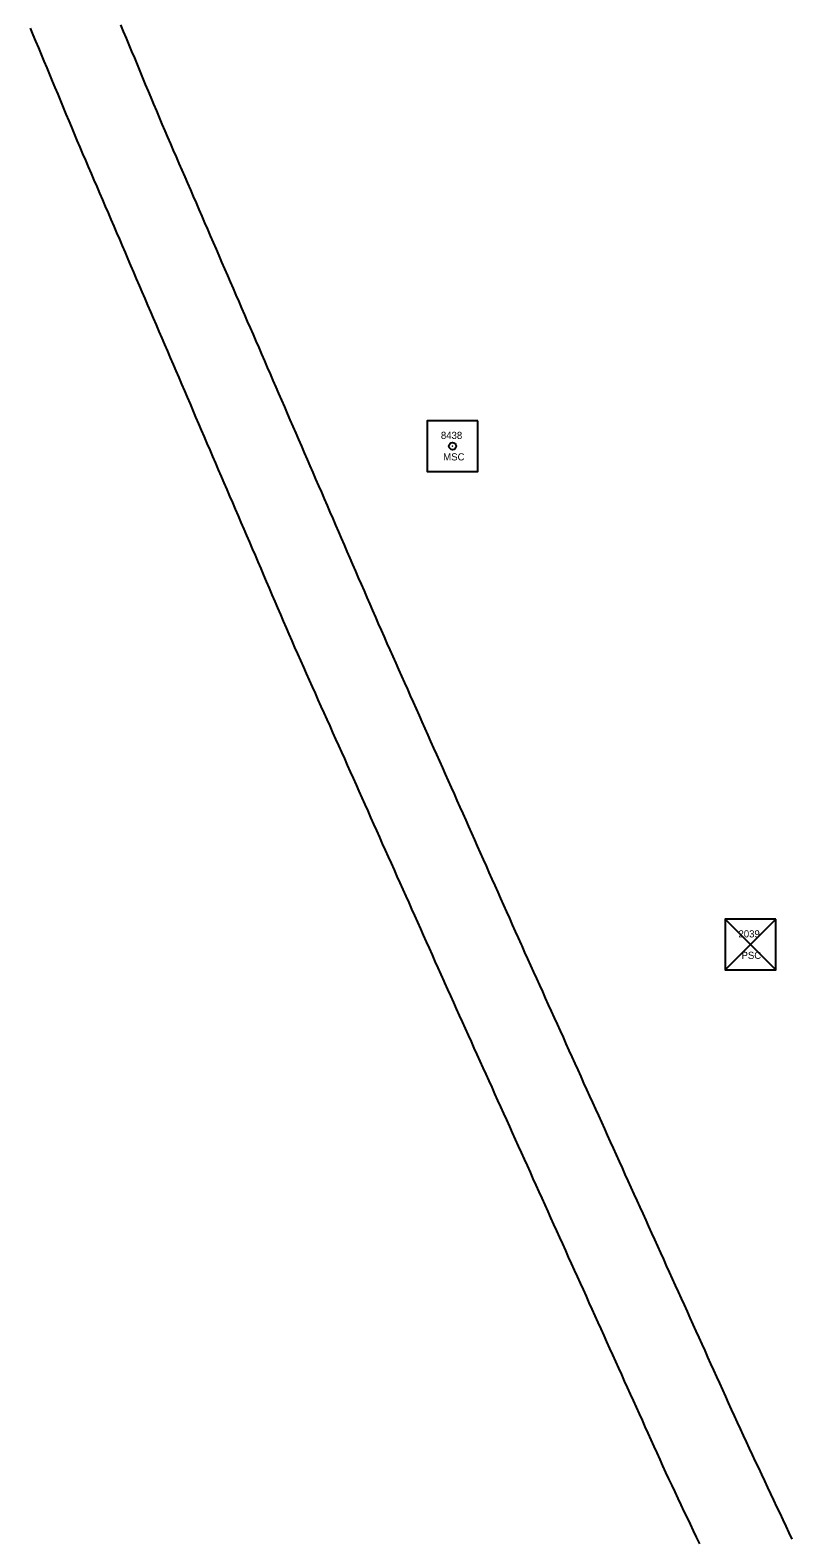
# Model space of a CAD drawing. Extents: x 205929 to 2357175, y -1785700 to 846739.
# Drawn here: x 2011940.5 to 2012046.8, y 825874.3 to 826084.7 of the extents above; entities that cross this region are included whole.
import ezdxf

# ---------------------------------------------------------------- set-up
doc = ezdxf.new("R2010")
doc.units = 0
for name, color, linetype in [('RD_HC_Survey', 7, 'Continuous'), ('RD_HC_txCode', 7, 'Continuous'), ('RD_Sketch1', 7, 'Continuous'), ('RD_SMD_Locator', 7, 'Continuous')]:
    doc.layers.add(name, color=color, linetype=linetype)

msp = doc.modelspace()

# ---------------------------------------------------------------- linework, layer by layer
at = {"layer": 'RD_HC_Survey'}
for p, q in [((2012037.49, 825960.58), (2012044.56, 825953.51)), ((2012044.56, 825960.58), (2012037.49, 825953.51)), ((2012044.56, 825960.58), (2012037.49, 825960.58)), ((2012037.49, 825960.58), (2012041.03, 825957.05)), ((2012041.03, 825957.05), (2012044.56, 825960.58)), ((2012041.03, 825957.05), (2012037.49, 825953.51)), ((2012044.56, 825953.51), (2012041.03, 825957.05)), ((2012037.49, 825953.51), (2012044.56, 825953.51))]:
    msp.add_line(p, q, dxfattribs=at)
for points in [[(2012002.98, 826030.15), (2011995.91, 826030.15), (2011995.91, 826023.08), (2012002.98, 826023.08)], [(2012044.56, 825960.58), (2012037.49, 825960.58), (2012037.49, 825953.51), (2012044.56, 825953.51)]]:
    msp.add_lwpolyline(points, close=True, dxfattribs=at)
msp.add_circle((2011999.44, 826026.62), 0.5, dxfattribs=at)
at = {"layer": 'RD_Sketch1'}
for points in [[(2011953.09, 826085.4), (2011953.47, 826084.48), (2011953.86, 826083.56), (2011954.24, 826082.63), (2011954.62, 826081.71), (2011955.01, 826080.79), (2011955.39, 826079.86), (2011955.77, 826078.94), (2011956.16, 826078.02), (2011956.54, 826077.09), (2011956.93, 826076.17), (2011957.31, 826075.25), (2011957.69, 826074.32), (2011958.08, 826073.4), (2011958.46, 826072.48), (2011958.86, 826071.56), (2011959.25, 826070.64), (2011959.65, 826069.72), (2011960.05, 826068.8), (2011960.45, 826067.89), (2011960.84, 826066.97), (2011961.24, 826066.05), (2011961.64, 826065.13), (2011962.04, 826064.22), (2011962.43, 826063.3), (2011962.83, 826062.38), (2011963.23, 826061.46), (2011963.63, 826060.55), (2011964.02, 826059.63), (2011964.42, 826058.71), (2011964.82, 826057.79), (2011965.22, 826056.88), (2011965.61, 826055.96), (2011966.01, 826055.04), (2011966.41, 826054.12), (2011966.81, 826053.21), (2011967.2, 826052.29), (2011967.6, 826051.37), (2011968, 826050.45), (2011968.4, 826049.54), (2011968.79, 826048.62), (2011969.19, 826047.7), (2011969.59, 826046.78), (2011969.99, 826045.87), (2011970.38, 826044.95), (2011970.78, 826044.03), (2011971.18, 826043.11), (2011971.58, 826042.2), (2011971.97, 826041.28), (2011972.37, 826040.36), (2011972.77, 826039.44), (2011973.17, 826038.53), (2011973.56, 826037.61), (2011973.96, 826036.69), (2011974.36, 826035.77), (2011974.76, 826034.86), (2011975.15, 826033.94), (2011975.55, 826033.02), (2011975.95, 826032.1), (2011976.35, 826031.19), (2011976.74, 826030.27), (2011977.14, 826029.35), (2011977.54, 826028.43), (2011977.94, 826027.52), (2011978.33, 826026.6), (2011978.73, 826025.68), (2011979.13, 826024.76), (2011979.53, 826023.85), (2011979.92, 826022.93), (2011980.32, 826022.01), (2011980.72, 826021.09), (2011981.12, 826020.18), (2011981.51, 826019.26), (2011981.91, 826018.34), (2011982.31, 826017.42), (2011982.71, 826016.51), (2011983.1, 826015.59), (2011983.5, 826014.67), (2011983.9, 826013.75), (2011984.3, 826012.84), (2011984.69, 826011.92), (2011985.09, 826011), (2011985.49, 826010.08), (2011985.89, 826009.17), (2011986.28, 826008.25), (2011986.68, 826007.33), (2011987.08, 826006.41), (2011987.48, 826005.5), (2011987.87, 826004.58), (2011988.27, 826003.66), (2011988.67, 826002.74), (2011989.07, 826001.83), (2011989.47, 826000.91), (2011989.87, 826000), (2011990.28, 825999.08), (2011990.69, 825998.17), (2011991.09, 825997.26), (2011991.5, 825996.34), (2011991.91, 825995.43), (2011992.31, 825994.52), (2011992.72, 825993.6), (2011993.13, 825992.69), (2011993.53, 825991.78), (2011993.94, 825990.86), (2011994.35, 825989.95), (2011994.76, 825989.04), (2011995.16, 825988.12), (2011995.57, 825987.21), (2011995.98, 825986.3), (2011996.38, 825985.38), (2011996.79, 825984.47), (2011997.2, 825983.56), (2011997.6, 825982.64), (2011998.01, 825981.73), (2011998.42, 825980.82), (2011998.83, 825979.9), (2011999.23, 825978.99), (2011999.64, 825978.08), (2012000.05, 825977.16), (2012000.45, 825976.25), (2012000.86, 825975.34), (2012001.27, 825974.42), (2012001.67, 825973.51), (2012002.08, 825972.6), (2012002.49, 825971.68), (2012002.89, 825970.77), (2012003.3, 825969.86), (2012003.71, 825968.94), (2012004.12, 825968.03), (2012004.52, 825967.12), (2012004.93, 825966.2), (2012005.34, 825965.29), (2012005.74, 825964.38), (2012006.15, 825963.46), (2012006.56, 825962.55), (2012006.96, 825961.63), (2012007.37, 825960.72), (2012007.78, 825959.81), (2012008.19, 825958.89), (2012008.59, 825957.98), (2012009, 825957.07), (2012009.09, 825956.86), (2012009.5, 825955.95), (2012009.91, 825955.04), (2012010.33, 825954.13), (2012010.74, 825953.22), (2012011.15, 825952.31), (2012011.56, 825951.4), (2012011.98, 825950.49), (2012012.39, 825949.58), (2012012.8, 825948.66), (2012013.21, 825947.75), (2012013.62, 825946.84), (2012014.04, 825945.93), (2012014.45, 825945.02), (2012014.86, 825944.11), (2012015.27, 825943.2), (2012015.68, 825942.29), (2012016.1, 825941.38), (2012016.51, 825940.46), (2012016.92, 825939.55), (2012017.33, 825938.64), (2012017.74, 825937.73), (2012018.16, 825936.82), (2012018.57, 825935.91), (2012018.98, 825935), (2012019.39, 825934.09), (2012019.81, 825933.18), (2012020.22, 825932.27), (2012020.63, 825931.35), (2012021.04, 825930.44), (2012021.45, 825929.53), (2012021.87, 825928.62), (2012022.28, 825927.71), (2012022.69, 825926.8), (2012023.1, 825925.89), (2012023.51, 825924.98), (2012023.93, 825924.07), (2012024.34, 825923.16), (2012024.75, 825922.24), (2012025.16, 825921.33), (2012025.57, 825920.42), (2012025.99, 825919.51), (2012026.4, 825918.6), (2012026.81, 825917.69), (2012027.22, 825916.78), (2012027.64, 825915.87), (2012028.05, 825914.96), (2012028.46, 825914.05), (2012028.87, 825913.13), (2012029.28, 825912.22), (2012029.7, 825911.31), (2012030.11, 825910.4), (2012030.52, 825909.49), (2012030.93, 825908.58), (2012031.34, 825907.67), (2012031.76, 825906.76), (2012032.17, 825905.85), (2012032.58, 825904.94), (2012032.99, 825904.02), (2012033.41, 825903.11), (2012033.82, 825902.2), (2012034.23, 825901.29), (2012034.64, 825900.38), (2012035.05, 825899.47), (2012035.47, 825898.56), (2012035.88, 825897.65), (2012036.29, 825896.74), (2012036.7, 825895.83), (2012037.11, 825894.91), (2012037.53, 825894), (2012037.94, 825893.09), (2012038.35, 825892.18), (2012038.76, 825891.27), (2012039.17, 825890.36), (2012039.59, 825889.45), (2012040, 825888.54), (2012040.43, 825887.63), (2012040.85, 825886.73), (2012041.28, 825885.82), (2012041.7, 825884.92), (2012042.13, 825884.02), (2012042.56, 825883.11), (2012042.98, 825882.21), (2012043.41, 825881.3), (2012043.83, 825880.4), (2012044.26, 825879.49), (2012044.68, 825878.59), (2012045.11, 825877.68), (2012045.54, 825876.78), (2012045.96, 825875.87), (2012046.39, 825874.97), (2012046.81, 825874.06)], [(2011940.46, 826084.96), (2011940.85, 826084.03), (2011941.23, 826083.11), (2011941.62, 826082.19), (2011942, 826081.26), (2011942.39, 826080.34), (2011942.77, 826079.42), (2011943.16, 826078.5), (2011943.54, 826077.57), (2011943.92, 826076.65), (2011944.31, 826075.73), (2011944.69, 826074.8), (2011945.08, 826073.88), (2011945.46, 826072.96), (2011945.85, 826072.03), (2011946.23, 826071.11), (2011946.62, 826070.19), (2011947, 826069.27), (2011947.39, 826068.35), (2011947.79, 826067.43), (2011948.18, 826066.51), (2011948.58, 826065.59), (2011948.97, 826064.67), (2011949.37, 826063.75), (2011949.76, 826062.83), (2011950.15, 826061.91), (2011950.55, 826060.99), (2011950.94, 826060.08), (2011951.34, 826059.16), (2011951.73, 826058.24), (2011952.13, 826057.32), (2011952.52, 826056.4), (2011952.92, 826055.48), (2011953.31, 826054.56), (2011953.71, 826053.64), (2011954.1, 826052.73), (2011954.49, 826051.81), (2011954.89, 826050.89), (2011955.28, 826049.97), (2011955.68, 826049.05), (2011956.07, 826048.13), (2011956.47, 826047.21), (2011956.86, 826046.29), (2011957.26, 826045.37), (2011957.65, 826044.46), (2011958.05, 826043.54), (2011958.44, 826042.62), (2011958.84, 826041.7), (2011959.23, 826040.78), (2011959.62, 826039.86), (2011960.02, 826038.94), (2011960.41, 826038.02), (2011960.81, 826037.11), (2011961.2, 826036.19), (2011961.6, 826035.27), (2011961.99, 826034.35), (2011962.39, 826033.43), (2011962.78, 826032.51), (2011963.18, 826031.59), (2011963.57, 826030.67), (2011963.96, 826029.75), (2011964.36, 826028.84), (2011964.75, 826027.92), (2011965.15, 826027), (2011965.54, 826026.08), (2011965.94, 826025.16), (2011966.33, 826024.24), (2011966.73, 826023.32), (2011967.12, 826022.4), (2011967.52, 826021.49), (2011967.91, 826020.57), (2011968.3, 826019.65), (2011968.7, 826018.73), (2011969.09, 826017.81), (2011969.49, 826016.89), (2011969.88, 826015.97), (2011970.28, 826015.05), (2011970.67, 826014.14), (2011971.07, 826013.22), (2011971.46, 826012.3), (2011971.86, 826011.38), (2011972.25, 826010.46), (2011972.65, 826009.54), (2011973.04, 826008.62), (2011973.43, 826007.7), (2011973.83, 826006.78), (2011974.22, 826005.87), (2011974.62, 826004.95), (2011975.01, 826004.03), (2011975.41, 826003.11), (2011975.8, 826002.19), (2011976.2, 826001.27), (2011976.59, 826000.35), (2011976.99, 825999.43), (2011977.39, 825998.52), (2011977.8, 825997.61), (2011978.2, 825996.69), (2011978.61, 825995.78), (2011979.02, 825994.87), (2011979.43, 825993.95), (2011979.84, 825993.04), (2011980.24, 825992.13), (2011980.65, 825991.22), (2011981.06, 825990.3), (2011981.47, 825989.39), (2011981.88, 825988.48), (2011982.29, 825987.56), (2011982.69, 825986.65), (2011983.1, 825985.74), (2011983.51, 825984.83), (2011983.92, 825983.91), (2011984.33, 825983), (2011984.73, 825982.09), (2011985.14, 825981.17), (2011985.55, 825980.26), (2011985.96, 825979.35), (2011986.37, 825978.44), (2011986.78, 825977.52), (2011987.18, 825976.61), (2011987.59, 825975.7), (2011988, 825974.78), (2011988.41, 825973.87), (2011988.82, 825972.96), (2011989.23, 825972.05), (2011989.63, 825971.13), (2011990.04, 825970.22), (2011990.45, 825969.31), (2011990.86, 825968.39), (2011991.27, 825967.48), (2011991.67, 825966.57), (2011992.08, 825965.66), (2011992.49, 825964.74), (2011992.9, 825963.83), (2011993.31, 825962.92), (2011993.72, 825962), (2011994.12, 825961.09), (2011994.53, 825960.18), (2011994.94, 825959.27), (2011995.35, 825958.35), (2011995.76, 825957.44), (2011996.16, 825956.53), (2011996.57, 825955.61), (2011996.98, 825954.7), (2011997.39, 825953.79), (2011997.8, 825952.88), (2011998.21, 825951.96), (2011998.32, 825951.72), (2011998.73, 825950.8), (2011999.14, 825949.89), (2011999.55, 825948.98), (2011999.96, 825948.07), (2012000.37, 825947.16), (2012000.79, 825946.25), (2012001.2, 825945.34), (2012001.61, 825944.43), (2012002.02, 825943.51), (2012002.43, 825942.6), (2012002.84, 825941.69), (2012003.25, 825940.78), (2012003.67, 825939.87), (2012004.08, 825938.96), (2012004.49, 825938.05), (2012004.9, 825937.14), (2012005.31, 825936.22), (2012005.72, 825935.31), (2012006.13, 825934.4), (2012006.55, 825933.49), (2012006.96, 825932.58), (2012007.37, 825931.67), (2012007.78, 825930.76), (2012008.19, 825929.85), (2012008.6, 825928.94), (2012009.02, 825928.02), (2012009.43, 825927.11), (2012009.84, 825926.2), (2012010.25, 825925.29), (2012010.66, 825924.38), (2012011.07, 825923.47), (2012011.48, 825922.56), (2012011.9, 825921.65), (2012012.31, 825920.73), (2012012.72, 825919.82), (2012013.13, 825918.91), (2012013.54, 825918), (2012013.95, 825917.09), (2012014.36, 825916.18), (2012014.78, 825915.27), (2012015.19, 825914.36), (2012015.6, 825913.44), (2012016.01, 825912.53), (2012016.42, 825911.62), (2012016.83, 825910.71), (2012017.25, 825909.8), (2012017.66, 825908.89), (2012018.07, 825907.98), (2012018.48, 825907.07), (2012018.89, 825906.15), (2012019.3, 825905.24), (2012019.71, 825904.33), (2012020.13, 825903.42), (2012020.54, 825902.51), (2012020.95, 825901.6), (2012021.36, 825900.69), (2012021.77, 825899.78), (2012022.18, 825898.86), (2012022.59, 825897.95), (2012023.01, 825897.04), (2012023.42, 825896.13), (2012023.83, 825895.22), (2012024.24, 825894.31), (2012024.65, 825893.4), (2012025.06, 825892.49), (2012025.47, 825891.58), (2012025.89, 825890.66), (2012026.3, 825889.75), (2012026.71, 825888.84), (2012027.12, 825887.93), (2012027.53, 825887.02), (2012027.94, 825886.11), (2012028.36, 825885.2), (2012028.77, 825884.29), (2012029.18, 825883.37), (2012029.6, 825882.47), (2012030.03, 825881.56), (2012030.46, 825880.66), (2012030.89, 825879.76), (2012031.32, 825878.86), (2012031.75, 825877.95), (2012032.18, 825877.05), (2012032.61, 825876.15), (2012033.04, 825875.24), (2012033.47, 825874.34), (2012033.9, 825873.44)]]:
    msp.add_lwpolyline(points, dxfattribs=at)
at = {"layer": 'RD_SMD_Locator'}
for centre in [(2011999.44, 826026.62), (2012041.03, 825957.05)]:
    msp.add_circle(centre, 0.001, dxfattribs=at)

# ---------------------------------------------------------------- texts
at = {"layer": 'RD_HC_txCode'}
for s, p in [('8438', (2011997.81, 826027.62)), ('MSC', (2011998.13, 826024.62)), ('2039', (2012039.36, 825958.05)), ('PSC', (2012039.78, 825955.05))]:
    msp.add_text(s, height=1, dxfattribs=at).set_placement(p)

doc.saveas('drawing.dxf')
